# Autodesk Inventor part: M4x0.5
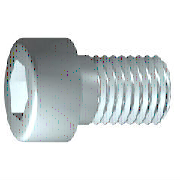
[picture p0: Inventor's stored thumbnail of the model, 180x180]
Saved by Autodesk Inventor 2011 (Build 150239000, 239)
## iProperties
IsCustomPart: 1
Company: 한국ATC센터
Created: 2014-11
Part Number: M4x0.5
Material: 강, 연강
Description: 6각머리 태핑 나사
Document SubType Name: Modeling
Standard: KS B 1003
Designer: KYOUNG IL JANG
Standards Organization: KS
Language: ko-KR
Size Designation: M 4 x 16
Categories: <MemberInstance><Categories><Category DisplayName="조임쇠" InternalName="e4da775c-781d-43d5-af7c-5136215cf5a6" Mnemonic="FSTN"><Category DisplayName="볼트" InternalN
Density: 7.86 g/cm^3
Mass: 2.62973 g
Surface Area: 3.81119 cm^2
Volume: 0.334572 cm^3
Author: KYOUNG IL JANG
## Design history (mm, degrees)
body "Solid1"
workplane "Work Plane1"
fillet "Fillet2" dims "d30" = 0.1 (= R)
revolve "본체" stored, may be unused: angle "d10" = 90 deg
sketch "스케치2"
  geometry: L1 (0, -4.9)-(0, 4.9) reference; L2 (-4.9, 0)-(4.9, 0) reference; L3 (1.732, 0)-(0.866, -1.5); L4 (0.866, -1.5)-(-0.866, -1.5); L5 (-0.866, -1.5)-(-1.732, 0); L6 (-1.732, 0)-(-0.866, 1.5); L7 (-0.866, 1.5)-(0.866, 1.5); L8 (0.866, 1.5)-(1.732, 0); 2 further points
  constraints: 12 end point, 1 coincident, 1 horizontal alignment, 1 point on line, 12 other
extrude "슬롯" join sketch "스케치2" stored distance "d11" = 10; taper "d12" = 0 deg
fillet "모깎기1" dims "d17" = 0.4 (= RR)
feature "스레드" dims "d13" = 14.25 (= GEL), "d14" = 0
chamfer "모따기1" distance "d15" = 0.42941 (= -0.5 x SPD + 0.5 x GD); stored, may be unused: second distance "d16" = 0.42941 (= GUL), angle "d27" = 45 deg
sketch "스케치1"
  geometry: L1 (-1, 0)-(16, 0); L2 (16, 0)-(16, 2); L3 (16, 2)-(1.75, 2); L4 (1.75, 2)-(1.32, 2); L5 (1.32, 2)-(0, 2); L6 (0, 2)-(0, 3.5); L7 (0, 3.5)-(-4, 3.5); L8 (-4, 3.5)-(-4, 1.732); L9 (-4, 1.732)-(-2, 1.732); L10 (-2, 1.732)-(-1, 0); L11 (-8, 0)-(20, 0) reference; L12 (0, -0.7)-(0, 4.2) reference; L13 (1.75, 2)-(0, 2)
  constraints: 22 end point, 6 parallel, 2 collinear, 2 perpendicular, 1 horizontal, 1 point on line
  dimensions: "d1" = 14.25 distance from line of L3.end L2 (= GEL); "d2" = 0.42952 distance of L4.end L3.end (computed from GAL); "d3" = 4 distance between parallel lines of L8 L6 (= KOH); "d4" = 2 distance of L8.end L9.end (= INTI); "d5" = 60 deg angle of L10 L1; "d6" = 4 diameter of L3 L1 (= GD); "d7" = 4 diameter of L5 L1 (= BDM); "d8" = 3.4641 diameter of L9 L1 (= 1.1547 x SW); "d9" = 7 diameter of L7 L1 (= KOD); "d26" = 16 distance between parallel lines of L12 L2 (= NLG)
other parameters: "GD" = 4 (= NND) [user parameter; used in 2 equation terms], "NLG" = 16 [user parameter; used in 1 equation term], "GEL" = 14.25 [user parameter; used in 2 equation terms], "KOD" = 7 [user parameter; used in 1 equation term], "KOH" = 4 [user parameter; used in 1 equation term], "INTI" = 2 [user parameter; used in 1 equation term], "GAL" = 0.42941 (= 0.61345 x PTC) [user parameter; used in 1 equation term], "GUL" = 0.42941 (= 0.61345 x PTC) [user parameter; used in 1 equation term], "BDM" = 4 (= NND) [user parameter; used in 1 equation term], "SW" = 3 [user parameter; used in 2 equation terms], "RR" = 0.4 [user parameter; used in 1 equation term], "SPD" = 3.14117 (= NND - 1.2269 x PTC) [user parameter; used in 1 equation term], "d19" = 0, "d28" = 0, "d29" = 0, "R" = 0.1 [user parameter; used in 1 equation term], "PHH" = 0.2 [user parameter], "GD1" = 3.14117 (= THREADDIA - 1.2269 x PTC) [user parameter], "THREADDIA" = 4 [user parameter; used in 1 equation term], "FAWI" = 45 deg [user parameter], "TPU" = 14.28571 (computed from PTC) [user parameter], "PTC" = 0.7 [user parameter; used in 5 equation terms], "NND" = 4 [user parameter; used in 3 equation terms], "TOA" = 30 deg [user parameter], "E0" = 3.465 (= 1.155 x SW) [user parameter]
